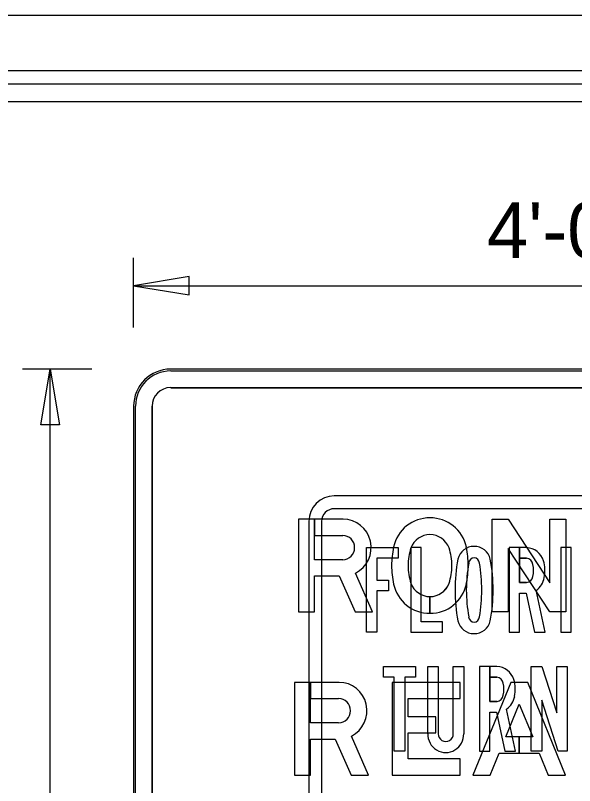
# Model space of a CAD drawing. Extents: x 17890628 to 17890844, y 17897693 to 17898031.
# Drawn here: x 17890741.73 to 17890750.53, y 17897987.69 to 17897999.81 of the extents above; entities that cross this region are included whole.
import ezdxf

# ---------------------------------------------------------------- set-up
doc = ezdxf.new("R2010")
doc.units = 0
for name, color, linetype in [('GSBWFill', 7, 'Continuous'), ('GSColorFill', 7, 'Continuous'), ('GSDims', 7, 'Continuous'), ('GSOutline', 7, 'Continuous'), ('PlotBorder_dp', 7, 'Continuous'), ('SheetBorder_dp', 7, 'Continuous'), ('SheetLinesMisc2_dp', 7, 'Continuous')]:
    doc.layers.add(name, color=color, linetype=linetype)

msp = doc.modelspace()

# ---------------------------------------------------------------- linework, layer by layer
at = {"layer": 'GSBWFill'}
for p, q in [((17890757.007, 17897994.243), (17890744.174, 17897994.243)), ((17890744.174, 17897993.951), (17890757.007, 17897993.951)), ((17890743.59, 17897993.66), (17890743.59, 17897980.826)), ((17890743.882, 17897980.826), (17890743.882, 17897993.66)), ((17890748.256, 17897990.663), (17890748.256, 17897990.401)), ((17890748.256, 17897990.401), (17890748.256, 17897990.663))]:
    msp.add_line(p, q, dxfattribs=at)
for points in [[(17890746.882, 17897991.244), (17890746.439, 17897991.244), (17890746.439, 17897991.88), (17890746.188, 17897991.88), (17890746.188, 17897990.422)], [(17890746.89, 17897991.88), (17890746.439, 17897991.88), (17890746.439, 17897991.625), (17890746.882, 17897991.625)], [(17890746.188, 17897990.422), (17890746.439, 17897990.422), (17890746.439, 17897990.989), (17890746.827, 17897990.989), (17890747.076, 17897990.422), (17890747.351, 17897990.422), (17890747.082, 17897991.034)], [(17890746.818, 17897988.677), (17890746.376, 17897988.677), (17890746.376, 17897989.314), (17890746.125, 17897989.314), (17890746.125, 17897987.855)], [(17890746.826, 17897989.314), (17890746.376, 17897989.314), (17890746.376, 17897989.059), (17890746.818, 17897989.059)], [(17890746.125, 17897987.855), (17890746.376, 17897987.855), (17890746.376, 17897988.422), (17890746.764, 17897988.422), (17890747.013, 17897987.855), (17890747.288, 17897987.855), (17890747.019, 17897988.467)]]:
    msp.add_lwpolyline(points, dxfattribs=at)
for points in [[(17890749.485, 17897991.88), (17890750.145, 17897990.88), (17890750.145, 17897991.88), (17890750.397, 17897991.88), (17890750.397, 17897990.422), (17890750.145, 17897990.422), (17890749.485, 17897991.422), (17890749.485, 17897990.422), (17890749.233, 17897990.422), (17890749.233, 17897991.88)], [(17890748.732, 17897988.111), (17890747.913, 17897988.111), (17890747.913, 17897988.517), (17890748.347, 17897988.517), (17890748.347, 17897988.773), (17890747.913, 17897988.773), (17890747.913, 17897989.059), (17890748.732, 17897989.059), (17890748.732, 17897989.314), (17890747.662, 17897989.314), (17890747.662, 17897987.855), (17890748.732, 17897987.855)], [(17890749.346, 17897988.199), (17890749.662, 17897988.199), (17890749.662, 17897988.454), (17890749.45, 17897988.454), (17890749.662, 17897988.972), (17890749.874, 17897988.454), (17890749.662, 17897988.454), (17890749.662, 17897988.199), (17890749.978, 17897988.199), (17890750.119, 17897987.855), (17890750.391, 17897987.855), (17890749.795, 17897989.314), (17890749.53, 17897989.314), (17890748.933, 17897987.855), (17890749.205, 17897987.855)]]:
    msp.add_lwpolyline(points, close=True, dxfattribs=at)
for radius in [0.583, 0.292]:
    msp.add_arc((17890744.174, 17897993.66), radius, 90, 180, dxfattribs=at)
for centre, major_axis, start_param, end_param in [((17890746.89, 17897991.435), (0, 0.446), 3.595687, 6.283185), ((17890748.248, 17897991.315), (0, 0.587), 6.268906, 7.635847), ((17890748.265, 17897991.315), (0, 0.587), 4.930523, 6.297464), ((17890746.882, 17897991.435), (0, 0.191), 3.141593, 6.283185), ((17890748.259, 17897991.307), (0, 0.332), 0.00795, 1.191969), ((17890748.254, 17897991.307), (0, 0.332), 5.091216, 6.275236), ((17890749.072, 17897991.144), (0, 1.441), 1.362764, 1.565867), ((17890748.791, 17897991.153), (0, 0.892), 1.25511, 1.572924), ((17890747.722, 17897991.153), (0, 0.892), 4.710262, 5.028075), ((17890747.44, 17897991.144), (0, 1.441), 4.717319, 4.920421), ((17890749.072, 17897991.158), (0, 1.441), 1.575726, 1.778829), ((17890748.791, 17897991.149), (0, 0.892), 1.568669, 1.886482), ((17890747.722, 17897991.149), (0, 0.892), 4.396703, 4.714516), ((17890747.44, 17897991.158), (0, 1.441), 4.504356, 4.707459), ((17890748.248, 17897990.988), (0, 0.587), 1.788931, 3.155871), ((17890748.259, 17897990.995), (0, 0.332), 1.949624, 3.133643), ((17890748.254, 17897990.995), (0, 0.332), 3.149762, 4.333562), ((17890748.265, 17897990.988), (0, 0.587), 3.127438, 4.494255), ((17890746.826, 17897988.868), (0, 0.446), 3.595687, 6.283185), ((17890746.818, 17897988.868), (0, 0.191), 3.141593, 6.283185)]:
    msp.add_ellipse(centre, major_axis=major_axis, ratio=0.985, start_param=start_param, end_param=end_param, dxfattribs=at)
at = {"layer": 'GSColorFill'}
for p, q in [((17890757.007, 17897994.243), (17890744.174, 17897994.243)), ((17890757.007, 17897994.243), (17890744.174, 17897994.243)), ((17890757.007, 17897994.243), (17890744.174, 17897994.243)), ((17890744.174, 17897994.214), (17890757.007, 17897994.214)), ((17890744.174, 17897993.951), (17890757.007, 17897993.951)), ((17890743.59, 17897993.66), (17890743.59, 17897980.826)), ((17890743.59, 17897993.66), (17890743.59, 17897980.826)), ((17890743.59, 17897993.66), (17890743.59, 17897980.826)), ((17890743.619, 17897980.826), (17890743.619, 17897993.66)), ((17890743.882, 17897980.826), (17890743.882, 17897993.66)), ((17890748.256, 17897990.663), (17890748.256, 17897990.401)), ((17890748.256, 17897990.401), (17890748.256, 17897990.663))]:
    msp.add_line(p, q, dxfattribs=at)
for points in [[(17890746.882, 17897991.244), (17890746.439, 17897991.244), (17890746.439, 17897991.88), (17890746.188, 17897991.88), (17890746.188, 17897990.422)], [(17890746.89, 17897991.88), (17890746.439, 17897991.88), (17890746.439, 17897991.625), (17890746.882, 17897991.625)], [(17890746.188, 17897990.422), (17890746.439, 17897990.422), (17890746.439, 17897990.989), (17890746.827, 17897990.989), (17890747.076, 17897990.422), (17890747.351, 17897990.422), (17890747.082, 17897991.034)], [(17890746.818, 17897988.677), (17890746.376, 17897988.677), (17890746.376, 17897989.314), (17890746.125, 17897989.314), (17890746.125, 17897987.855)], [(17890746.826, 17897989.314), (17890746.376, 17897989.314), (17890746.376, 17897989.059), (17890746.818, 17897989.059)], [(17890746.125, 17897987.855), (17890746.376, 17897987.855), (17890746.376, 17897988.422), (17890746.764, 17897988.422), (17890747.013, 17897987.855), (17890747.288, 17897987.855), (17890747.019, 17897988.467)]]:
    msp.add_lwpolyline(points, dxfattribs=at)
for points in [[(17890749.485, 17897991.88), (17890750.145, 17897990.88), (17890750.145, 17897991.88), (17890750.397, 17897991.88), (17890750.397, 17897990.422), (17890750.145, 17897990.422), (17890749.485, 17897991.422), (17890749.485, 17897990.422), (17890749.233, 17897990.422), (17890749.233, 17897991.88)], [(17890748.732, 17897988.111), (17890747.913, 17897988.111), (17890747.913, 17897988.517), (17890748.347, 17897988.517), (17890748.347, 17897988.773), (17890747.913, 17897988.773), (17890747.913, 17897989.059), (17890748.732, 17897989.059), (17890748.732, 17897989.314), (17890747.662, 17897989.314), (17890747.662, 17897987.855), (17890748.732, 17897987.855)], [(17890749.346, 17897988.199), (17890749.662, 17897988.199), (17890749.662, 17897988.454), (17890749.45, 17897988.454), (17890749.662, 17897988.972), (17890749.874, 17897988.454), (17890749.662, 17897988.454), (17890749.662, 17897988.199), (17890749.978, 17897988.199), (17890750.119, 17897987.855), (17890750.391, 17897987.855), (17890749.795, 17897989.314), (17890749.53, 17897989.314), (17890748.933, 17897987.855), (17890749.205, 17897987.855)]]:
    msp.add_lwpolyline(points, close=True, dxfattribs=at)
for radius in [0.583, 0.583, 0.583, 0.554, 0.292]:
    msp.add_arc((17890744.174, 17897993.66), radius, 90, 180, dxfattribs=at)
for centre, major_axis, start_param, end_param in [((17890746.89, 17897991.435), (0, 0.446), 3.595687, 6.283185), ((17890748.248, 17897991.315), (0, 0.587), 6.268906, 7.635847), ((17890748.265, 17897991.315), (0, 0.587), 4.930523, 6.297464), ((17890746.882, 17897991.435), (0, 0.191), 3.141593, 6.283185), ((17890748.259, 17897991.307), (0, 0.332), 0.00795, 1.191969), ((17890748.254, 17897991.307), (0, 0.332), 5.091216, 6.275236), ((17890749.072, 17897991.144), (0, 1.441), 1.362764, 1.565867), ((17890748.791, 17897991.153), (0, 0.892), 1.25511, 1.572924), ((17890747.722, 17897991.153), (0, 0.892), 4.710262, 5.028075), ((17890747.44, 17897991.144), (0, 1.441), 4.717319, 4.920421), ((17890749.072, 17897991.158), (0, 1.441), 1.575726, 1.778829), ((17890748.791, 17897991.149), (0, 0.892), 1.568669, 1.886482), ((17890747.722, 17897991.149), (0, 0.892), 4.396703, 4.714516), ((17890747.44, 17897991.158), (0, 1.441), 4.504356, 4.707459), ((17890748.248, 17897990.988), (0, 0.587), 1.788931, 3.155871), ((17890748.259, 17897990.995), (0, 0.332), 1.949624, 3.133643), ((17890748.254, 17897990.995), (0, 0.332), 3.149762, 4.333562), ((17890748.265, 17897990.988), (0, 0.587), 3.127438, 4.494255), ((17890746.826, 17897988.868), (0, 0.446), 3.595687, 6.283185), ((17890746.818, 17897988.868), (0, 0.191), 3.141593, 6.283185)]:
    msp.add_ellipse(centre, major_axis=major_axis, ratio=0.985, start_param=start_param, end_param=end_param, dxfattribs=at)
at = {"layer": 'GSDims'}
for p, q in [((17890743.59, 17897994.899), (17890743.59, 17897995.993)), ((17890743.59, 17897995.555), (17890757.59, 17897995.555)), ((17890742.934, 17897994.243), (17890741.84, 17897994.243)), ((17890742.278, 17897984.297), (17890742.278, 17897994.243))]:
    msp.add_line(p, q, dxfattribs=at)
for points in [[(17890743.59, 17897995.555), (17890744.465, 17897995.41), (17890744.465, 17897995.701)], [(17890742.278, 17897994.243), (17890742.424, 17897993.368), (17890742.132, 17897993.368)]]:
    msp.add_lwpolyline(points, close=True, dxfattribs=at)
at = {"layer": 'GSOutline'}
for p, q in [((17890757.007, 17897994.243), (17890744.174, 17897994.243)), ((17890757.007, 17897993.951), (17890744.174, 17897993.951)), ((17890743.59, 17897993.66), (17890743.59, 17897980.826)), ((17890743.882, 17897993.66), (17890743.882, 17897980.826)), ((17890753.95, 17897992.247), (17890746.75, 17897992.247)), ((17890753.95, 17897992.047), (17890746.75, 17897992.047)), ((17890746.35, 17897991.847), (17890746.35, 17897983.047)), ((17890746.55, 17897991.847), (17890746.55, 17897983.047)), ((17890746.882, 17897991.244), (17890746.439, 17897991.244)), ((17890746.818, 17897988.677), (17890746.376, 17897988.677)), ((17890748.623, 17897988.506), (17890748.623, 17897988.506)), ((17890748.623, 17897988.506), (17890748.623, 17897988.506)), ((17890748.623, 17897988.506), (17890748.623, 17897988.506))]:
    msp.add_line(p, q, dxfattribs=at)
for points in [[(17890746.89, 17897991.88), (17890746.188, 17897991.88), (17890746.188, 17897990.422), (17890746.439, 17897990.422), (17890746.439, 17897990.989), (17890746.827, 17897990.989)], [(17890746.439, 17897991.244), (17890746.439, 17897991.625), (17890746.882, 17897991.625)], [(17890749.778, 17897991.434), (17890749.504, 17897991.434), (17890749.504, 17897990.101), (17890749.668, 17897990.101), (17890749.668, 17897990.717), (17890749.771, 17897990.717), (17890749.901, 17897990.101)], [(17890749.668, 17897991.434), (17890749.504, 17897991.434), (17890749.504, 17897990.101), (17890749.668, 17897990.101), (17890749.668, 17897990.717), (17890749.771, 17897990.717), (17890749.901, 17897990.101), (17890750.068, 17897990.101), (17890749.929, 17897990.762)], [(17890749.668, 17897991.434), (17890749.504, 17897991.434), (17890749.504, 17897990.101), (17890749.668, 17897990.101), (17890749.668, 17897990.717), (17890749.771, 17897990.717), (17890749.901, 17897990.101), (17890750.068, 17897990.101), (17890749.929, 17897990.762)], [(17890749.778, 17897991.434), (17890749.668, 17897991.434), (17890749.668, 17897991.267), (17890749.778, 17897991.267)], [(17890749.778, 17897990.883), (17890749.668, 17897990.883), (17890749.668, 17897991.434)], [(17890749.778, 17897991.434), (17890749.668, 17897991.434), (17890749.668, 17897991.267), (17890749.778, 17897991.267)], [(17890749.778, 17897990.883), (17890749.668, 17897990.883), (17890749.668, 17897991.434)], [(17890749.778, 17897991.267), (17890749.668, 17897991.267), (17890749.668, 17897990.883), (17890749.778, 17897990.883)], [(17890746.827, 17897990.989), (17890747.076, 17897990.422), (17890747.351, 17897990.422), (17890747.082, 17897991.034)], [(17890749.901, 17897990.101), (17890750.068, 17897990.101), (17890749.929, 17897990.762)], [(17890748.223, 17897988.506), (17890748.223, 17897989.564), (17890748.387, 17897989.564), (17890748.387, 17897988.506)], [(17890748.223, 17897988.506), (17890748.223, 17897989.564), (17890748.387, 17897989.564), (17890748.387, 17897988.506)], [(17890748.223, 17897988.506), (17890748.223, 17897989.564), (17890748.387, 17897989.564), (17890748.387, 17897988.506)], [(17890748.623, 17897988.506), (17890748.623, 17897989.564), (17890748.787, 17897989.564), (17890748.787, 17897988.506)], [(17890748.623, 17897988.506), (17890748.623, 17897989.564), (17890748.787, 17897989.564), (17890748.787, 17897988.506)], [(17890748.623, 17897988.506), (17890748.623, 17897989.564), (17890748.787, 17897989.564), (17890748.787, 17897988.506)], [(17890749.311, 17897989.564), (17890749.037, 17897989.564), (17890749.037, 17897988.231), (17890749.201, 17897988.231), (17890749.201, 17897988.847), (17890749.304, 17897988.847), (17890749.434, 17897988.231)], [(17890749.201, 17897989.564), (17890749.037, 17897989.564), (17890749.037, 17897988.231), (17890749.201, 17897988.231), (17890749.201, 17897988.847), (17890749.304, 17897988.847), (17890749.434, 17897988.231), (17890749.602, 17897988.231), (17890749.463, 17897988.892)], [(17890749.201, 17897989.564), (17890749.037, 17897989.564), (17890749.037, 17897988.231), (17890749.201, 17897988.231), (17890749.201, 17897988.847), (17890749.304, 17897988.847), (17890749.434, 17897988.231), (17890749.602, 17897988.231), (17890749.463, 17897988.892)], [(17890749.311, 17897989.564), (17890749.201, 17897989.564), (17890749.201, 17897989.397), (17890749.311, 17897989.397)], [(17890749.311, 17897989.013), (17890749.201, 17897989.013), (17890749.201, 17897989.564)], [(17890749.311, 17897989.564), (17890749.201, 17897989.564), (17890749.201, 17897989.397), (17890749.311, 17897989.397)], [(17890749.311, 17897989.013), (17890749.201, 17897989.013), (17890749.201, 17897989.564)], [(17890746.826, 17897989.314), (17890746.125, 17897989.314), (17890746.125, 17897987.855), (17890746.376, 17897987.855), (17890746.376, 17897988.422), (17890746.764, 17897988.422)], [(17890749.311, 17897989.397), (17890749.201, 17897989.397), (17890749.201, 17897989.013), (17890749.311, 17897989.013)], [(17890746.376, 17897988.677), (17890746.376, 17897989.059), (17890746.818, 17897989.059)], [(17890749.434, 17897988.231), (17890749.602, 17897988.231), (17890749.463, 17897988.892)], [(17890746.764, 17897988.422), (17890747.013, 17897987.855), (17890747.288, 17897987.855), (17890747.019, 17897988.467)]]:
    msp.add_lwpolyline(points, dxfattribs=at)
for points in [[(17890749.485, 17897991.88), (17890750.145, 17897990.88), (17890750.145, 17897991.88), (17890750.397, 17897991.88), (17890750.397, 17897990.422), (17890750.145, 17897990.422), (17890749.485, 17897991.422), (17890749.485, 17897990.422), (17890749.233, 17897990.422), (17890749.233, 17897991.88)], [(17890747.604, 17897990.92), (17890747.604, 17897990.753), (17890747.422, 17897990.753), (17890747.422, 17897990.101), (17890747.258, 17897990.101), (17890747.258, 17897991.434), (17890747.757, 17897991.434), (17890747.757, 17897991.267), (17890747.422, 17897991.267), (17890747.422, 17897990.92)], [(17890748.118, 17897990.267), (17890748.118, 17897991.434), (17890747.954, 17897991.434), (17890747.954, 17897990.101), (17890748.453, 17897990.101), (17890748.453, 17897990.267)], [(17890750.482, 17897991.434), (17890750.318, 17897991.434), (17890750.318, 17897990.101), (17890750.482, 17897990.101)], [(17890748.026, 17897989.397), (17890747.858, 17897989.397), (17890747.858, 17897988.231), (17890747.694, 17897988.231), (17890747.694, 17897989.397), (17890747.526, 17897989.397), (17890747.526, 17897989.564), (17890748.026, 17897989.564)], [(17890750.015, 17897989.031), (17890750.015, 17897988.231), (17890749.851, 17897988.231), (17890749.851, 17897989.564), (17890750.015, 17897989.564), (17890750.252, 17897988.835), (17890750.252, 17897989.564), (17890750.416, 17897989.564), (17890750.416, 17897988.231), (17890750.275, 17897988.231)], [(17890748.732, 17897988.111), (17890747.913, 17897988.111), (17890747.913, 17897988.517), (17890748.347, 17897988.517), (17890748.347, 17897988.773), (17890747.913, 17897988.773), (17890747.913, 17897989.059), (17890748.732, 17897989.059), (17890748.732, 17897989.314), (17890747.662, 17897989.314), (17890747.662, 17897987.855), (17890748.732, 17897987.855)], [(17890749.978, 17897988.199), (17890750.119, 17897987.855), (17890750.391, 17897987.855), (17890749.795, 17897989.314), (17890749.53, 17897989.314), (17890748.933, 17897987.855), (17890749.205, 17897987.855), (17890749.346, 17897988.199)], [(17890749.662, 17897988.972), (17890749.874, 17897988.454), (17890749.45, 17897988.454)]]:
    msp.add_lwpolyline(points, close=True, dxfattribs=at)
for centre, radius in [((17890744.174, 17897993.66), 0.583), ((17890744.174, 17897993.66), 0.292), ((17890746.75, 17897991.847), 0.4), ((17890746.75, 17897991.847), 0.2)]:
    msp.add_arc(centre, radius, 90, 180, dxfattribs=at)
for centre, major_axis, start_param, end_param in [((17890746.89, 17897991.435), (0, 0.446), 3.595687, 6.283185), ((17890748.248, 17897991.315), (0, 0.587), 6.268906, 7.635847), ((17890748.265, 17897991.315), (0, 0.587), 4.930523, 6.297464), ((17890746.882, 17897991.435), (0, 0.191), 3.141593, 6.283185), ((17890748.259, 17897991.307), (0, 0.332), 0.00795, 1.191969), ((17890748.254, 17897991.307), (0, 0.332), 5.091216, 6.275236), ((17890749.072, 17897991.144), (0, 1.441), 1.362764, 1.565867), ((17890748.791, 17897991.153), (0, 0.892), 1.25511, 1.572924), ((17890747.722, 17897991.153), (0, 0.892), 4.710262, 5.028075), ((17890748.948, 17897991.19), (0, 0.264), 6.270788, 7.609689), ((17890748.948, 17897991.19), (0, 0.264), 6.270788, 7.609689), ((17890748.948, 17897991.19), (0, 0.264), 6.270788, 7.609689), ((17890747.44, 17897991.144), (0, 1.441), 4.717319, 4.920421), ((17890748.954, 17897991.19), (0, 0.264), 4.956682, 6.295583), ((17890748.954, 17897991.19), (0, 0.264), 4.956682, 6.295331), ((17890748.954, 17897991.19), (0, 0.264), 4.956682, 6.295331), ((17890749.763, 17897991.134), (0, 0.3), 5.030251, 6.233097), ((17890749.763, 17897991.134), (0, 0.3), 5.030251, 6.233097), ((17890749.763, 17897991.134), (0, 0.3), 5.030251, 6.233097), ((17890751.179, 17897990.779), (0, 2.566), 1.3849, 1.575497), ((17890751.179, 17897990.779), (0, 2.566), 1.3849, 1.575497), ((17890751.179, 17897990.779), (0, 2.566), 1.3849, 1.575497), ((17890748.96, 17897991.178), (0, 0.0974), 0.099923, 1.436755), ((17890748.96, 17897991.178), (0, 0.0974), 0.099923, 1.436755), ((17890748.96, 17897991.178), (0, 0.0974), 0.099923, 1.436755), ((17890748.941, 17897991.178), (0, 0.0974), 4.846431, 6.183262), ((17890748.941, 17897991.178), (0, 0.0974), 4.846431, 6.182575), ((17890748.941, 17897991.178), (0, 0.0974), 4.846431, 6.182575), ((17890746.722, 17897990.779), (0, 2.566), 4.707688, 4.898285), ((17890746.722, 17897990.779), (0, 2.566), 4.707688, 4.898285), ((17890746.722, 17897990.779), (0, 2.566), 4.707688, 4.898285), ((17890749.758, 17897991.145), (0, 0.124), 4.908761, 6.117799), ((17890749.758, 17897991.145), (0, 0.124), 4.908761, 6.117799), ((17890749.758, 17897991.145), (0, 0.124), 4.908761, 6.117799), ((17890749.541, 17897991.071), (0, 0.534), 4.509585, 5.011141), ((17890749.541, 17897991.071), (0, 0.534), 4.509585, 5.011141), ((17890749.541, 17897991.071), (0, 0.534), 4.509585, 5.011141), ((17890749.072, 17897991.158), (0, 1.441), 1.575726, 1.778829), ((17890748.791, 17897991.149), (0, 0.892), 1.568669, 1.886482), ((17890747.722, 17897991.149), (0, 0.892), 4.396703, 4.714516), ((17890751.437, 17897990.745), (0, 2.648), 1.401553, 1.562444), ((17890751.437, 17897990.745), (0, 2.648), 1.401553, 1.562444), ((17890751.437, 17897990.745), (0, 2.648), 1.401553, 1.562444), ((17890747.44, 17897991.158), (0, 1.441), 4.504356, 4.707459), ((17890746.465, 17897990.745), (0, 2.648), 4.720742, 4.881632), ((17890746.465, 17897990.745), (0, 2.648), 4.720742, 4.881632), ((17890746.465, 17897990.745), (0, 2.648), 4.720742, 4.881632), ((17890749.496, 17897991.078), (0, 0.398), 4.465322, 4.943449), ((17890749.496, 17897991.078), (0, 0.398), 4.465322, 4.943449), ((17890749.496, 17897991.078), (0, 0.398), 4.465322, 4.943449), ((17890749.762, 17897990.999), (0, 0.117), 3.278526, 4.557126), ((17890749.762, 17897990.999), (0, 0.117), 3.278526, 4.557126), ((17890749.762, 17897990.999), (0, 0.117), 3.278526, 4.557126), ((17890748.248, 17897990.988), (0, 0.587), 1.788931, 3.155871), ((17890748.259, 17897990.995), (0, 0.332), 1.949624, 3.133643), ((17890748.254, 17897990.995), (0, 0.332), 3.149542, 4.333562), ((17890748.265, 17897990.988), (0, 0.587), 3.127314, 4.494255), ((17890749.74, 17897991.026), (0, 0.327), 3.768896, 4.519364), ((17890749.74, 17897991.026), (0, 0.327), 3.768896, 4.519364), ((17890749.74, 17897991.026), (0, 0.327), 3.768896, 4.519364), ((17890751.179, 17897990.755), (0, 2.566), 1.566095, 1.756692), ((17890751.179, 17897990.755), (0, 2.566), 1.566095, 1.756692), ((17890751.179, 17897990.755), (0, 2.566), 1.566095, 1.756692), ((17890751.437, 17897990.789), (0, 2.648), 1.579149, 1.740039), ((17890751.437, 17897990.789), (0, 2.648), 1.579149, 1.740039), ((17890751.437, 17897990.789), (0, 2.648), 1.579149, 1.740039), ((17890746.465, 17897990.789), (0, 2.648), 4.543146, 4.704036), ((17890746.465, 17897990.789), (0, 2.648), 4.543146, 4.704036), ((17890746.465, 17897990.789), (0, 2.648), 4.543146, 4.704036), ((17890746.722, 17897990.755), (0, 2.566), 4.526493, 4.71709), ((17890746.722, 17897990.755), (0, 2.566), 4.526493, 4.71709), ((17890746.722, 17897990.755), (0, 2.566), 4.526493, 4.71709), ((17890748.948, 17897990.345), (0, 0.264), 1.815089, 3.15399), ((17890748.948, 17897990.345), (0, 0.264), 1.815089, 3.15399), ((17890748.948, 17897990.345), (0, 0.264), 1.815089, 3.15399), ((17890748.96, 17897990.356), (0, 0.0974), 1.704838, 3.04167), ((17890748.96, 17897990.356), (0, 0.0974), 1.704838, 3.04167), ((17890748.96, 17897990.356), (0, 0.0974), 1.704838, 3.04167), ((17890748.941, 17897990.356), (0, 0.0974), 3.241516, 4.578347), ((17890748.941, 17897990.356), (0, 0.0974), 3.241516, 4.578347), ((17890748.941, 17897990.356), (0, 0.0974), 3.241516, 4.578347), ((17890748.954, 17897990.345), (0, 0.264), 3.129195, 4.468096), ((17890748.954, 17897990.345), (0, 0.264), 3.129195, 4.468096), ((17890748.954, 17897990.345), (0, 0.264), 3.129195, 4.468096), ((17890749.296, 17897989.264), (0, 0.3), 5.030251, 6.233097), ((17890749.296, 17897989.264), (0, 0.3), 5.030251, 6.233097), ((17890749.296, 17897989.264), (0, 0.3), 5.030251, 6.233097), ((17890746.826, 17897988.868), (0, 0.446), 3.595687, 6.283185), ((17890749.291, 17897989.275), (0, 0.124), 4.908761, 6.117799), ((17890749.291, 17897989.275), (0, 0.124), 4.908761, 6.117799), ((17890749.291, 17897989.275), (0, 0.124), 4.908761, 6.117799), ((17890749.029, 17897989.208), (0, 0.398), 4.465322, 4.943449), ((17890749.029, 17897989.208), (0, 0.398), 4.465322, 4.943449), ((17890749.029, 17897989.208), (0, 0.398), 4.465322, 4.943449), ((17890749.074, 17897989.201), (0, 0.534), 4.509585, 5.011141), ((17890749.074, 17897989.201), (0, 0.534), 4.509585, 5.011141), ((17890749.074, 17897989.201), (0, 0.534), 4.509585, 5.011141), ((17890746.818, 17897988.868), (0, 0.191), 3.141593, 6.283185), ((17890749.296, 17897989.129), (0, 0.117), 3.278526, 4.557126), ((17890749.296, 17897989.129), (0, 0.117), 3.278526, 4.557126), ((17890749.296, 17897989.129), (0, 0.117), 3.278526, 4.557126), ((17890749.274, 17897989.156), (0, 0.327), 3.768896, 4.519364), ((17890749.274, 17897989.156), (0, 0.327), 3.768896, 4.519364), ((17890749.274, 17897989.156), (0, 0.327), 3.768896, 4.519364), ((17890748.505, 17897988.497), (0, 0.287), 1.539768, 4.743417), ((17890748.505, 17897988.497), (0, 0.287), 1.539768, 4.743417), ((17890748.505, 17897988.497), (0, 0.287), 1.539768, 4.743417), ((17890748.505, 17897988.502), (0, 0.12), 1.536895, 4.746291), ((17890748.505, 17897988.502), (0, 0.12), 1.536895, 4.746291), ((17890748.505, 17897988.502), (0, 0.12), 1.536895, 4.746291)]:
    msp.add_ellipse(centre, major_axis=major_axis, ratio=0.985, start_param=start_param, end_param=end_param, dxfattribs=at)
at = {"layer": 'PlotBorder_dp'}
msp.add_lwpolyline([(17890700.471, 17897907.61), (17890843.989, 17897907.61), (17890843.989, 17897999.809), (17890700.471, 17897999.809)], close=True, dxfattribs=at)
at = {"layer": 'SheetBorder_dp'}
msp.add_line((17890705.254, 17897998.94), (17890839.205, 17897998.94), dxfattribs=at)
at = {"layer": 'SheetLinesMisc2_dp'}
for p, q in [((17890705.5, 17897998.732), (17890839.233, 17897998.732)), ((17890726.429, 17897998.455), (17890771.912, 17897998.455))]:
    msp.add_line(p, q, dxfattribs=at)

# ---------------------------------------------------------------- texts
at = {"layer": 'GSDims'}
msp.add_text('4\'-0"', height=0.875, dxfattribs=at).set_placement((17890749.154, 17897995.993))

doc.saveas('drawing.dxf')
